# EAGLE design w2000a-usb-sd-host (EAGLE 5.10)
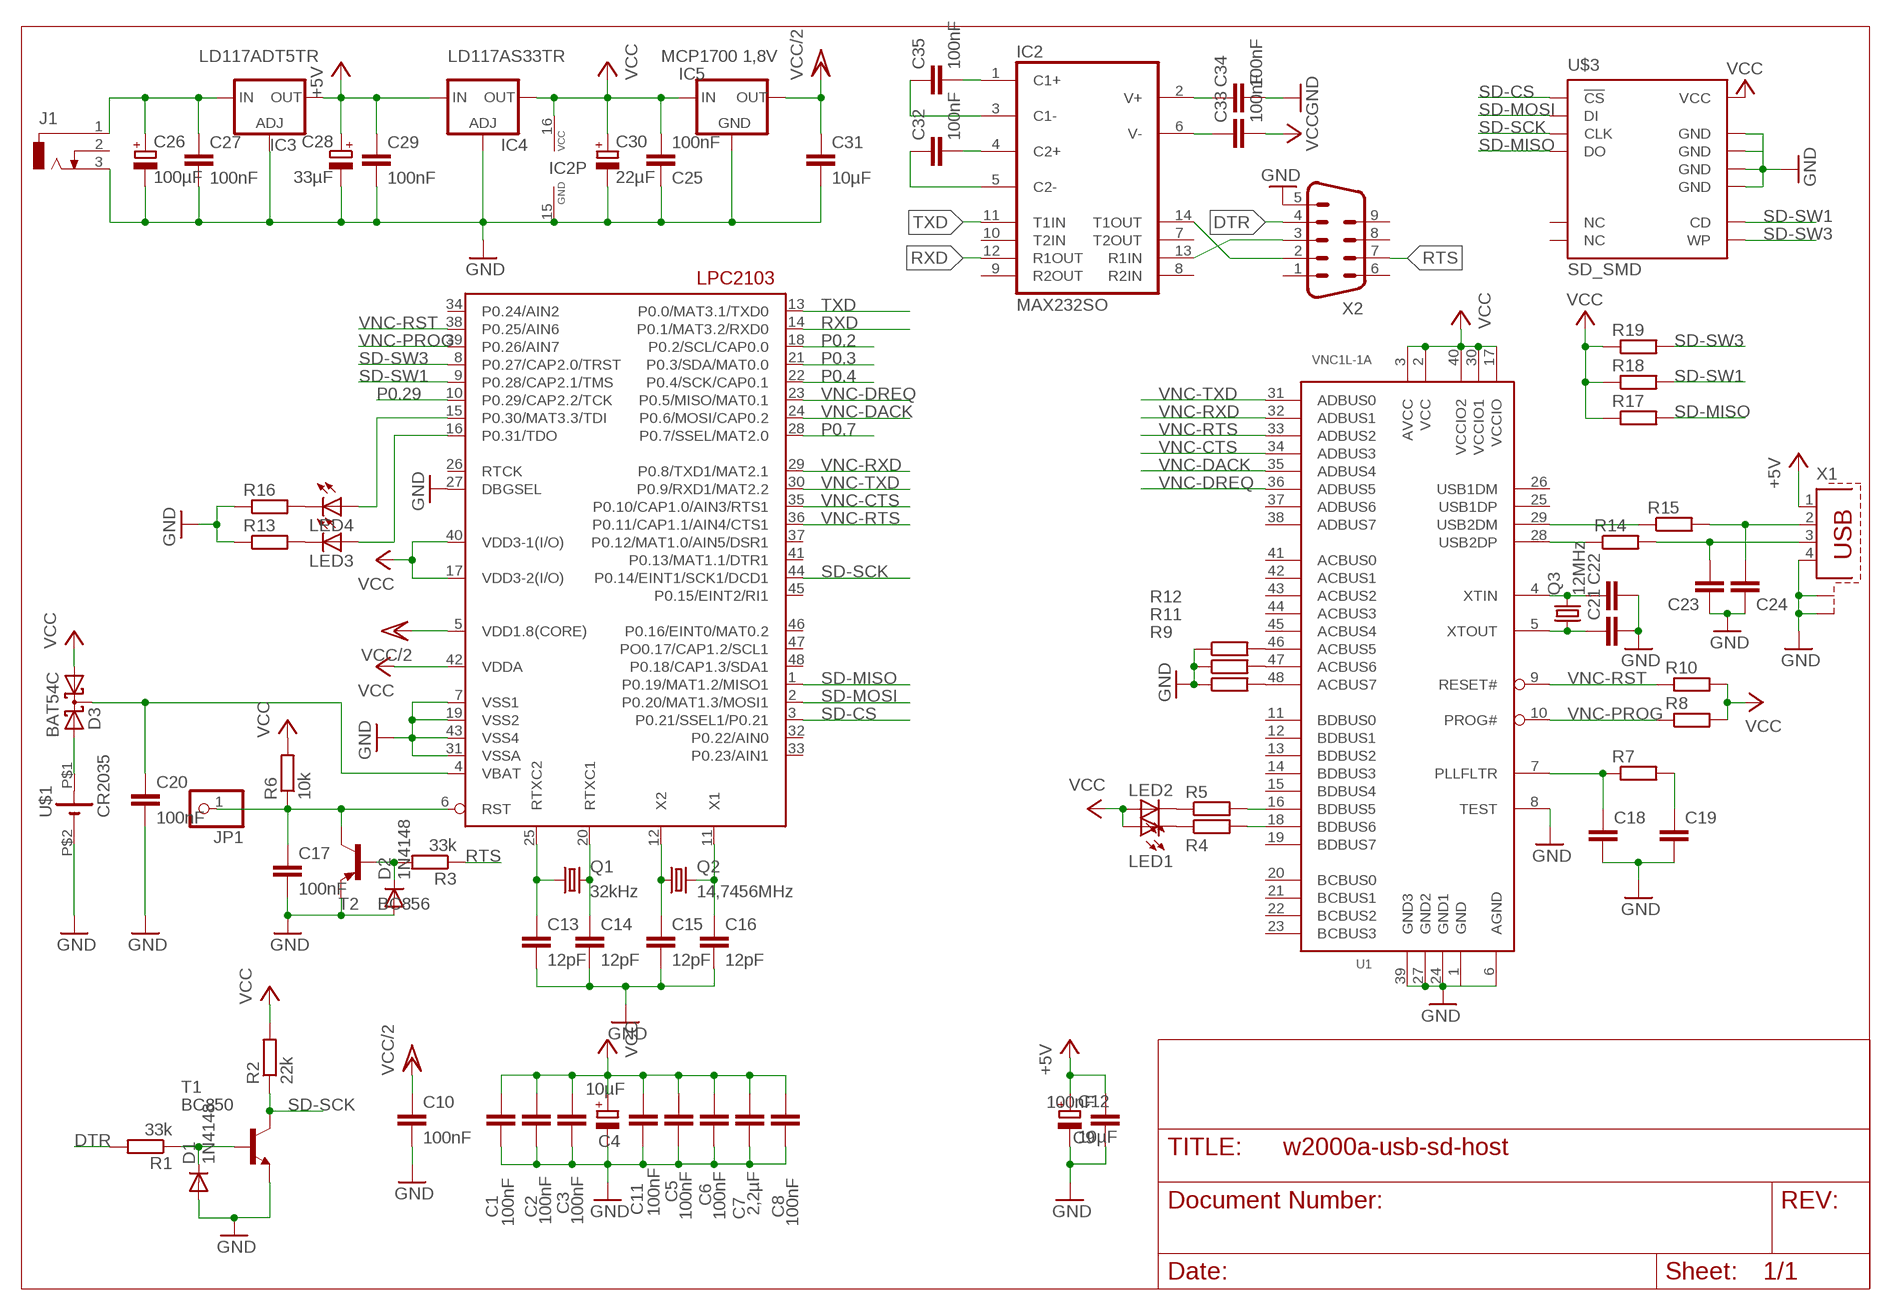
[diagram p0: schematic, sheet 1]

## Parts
C1  100nF  C-EUC0603  [C0603]
C2  100nF  C-EUC0603  [C0603]
C3  100nF  C-EUC0603  [C0603]
C4  100nF  C-EUC0603  [C0603]
C5  100nF  C-EUC0603  [C0603]
C6  100nF  C-EUC0603  [C0603]
C7  2,2µF  C-EUC0603  [C0603]
C8  100nF  C-EUC0603  [C0603]
C9  100nF  C-EUC0603  [C0603]
C10  100nF  C-EUC0603  [C0603]
C11  10µF  CPOL-EUSMCC  [SMC_C]
C12  10µF  CPOL-EUSMCC  [SMC_C]
C13  12pF  C-EUC0603  [C0603]
C14  12pF  C-EUC0603  [C0603]
C15  12pF  C-EUC0603  [C0603]
C16  12pF  C-EUC0603  [C0603]
C17  100nF  C-EUC0603  [C0603]
C18  C-EUC0603  [C0603]
C19  C-EUC0603  [C0603]
C20  100nF  C-EUC0603  [C0603]
C21  C-EUC0603  [C0603]
C22  C-EUC0603  [C0603]
C23  C-EUC0603  [C0603]
C24  C-EUC0603  [C0603]
C25  100nF  C-EUC0603  [C0603]
C26  100µF  CPOL-EUSMCD  [SMC_D]
C27  100nF  C-EUC0603  [C0603]
C28  33µF  CPOL-EUSMCB  [SMC_B]
C29  100nF  C-EUC0603  [C0603]
C30  22µF  CPOL-EU140CLH-0810  [140CLH-0810]
C31  10µF  C-EUC0603  [C0603]
C32  100nF  C-EUC0603  [C0603]
C33  100nF  C-EUC0603  [C0603]
C34  100nF  C-EUC0603  [C0603]
C35  100nF  C-EUC0603  [C0603]
D1  1N4148  1N4148MINIMELF  [MINIMELF]
D2  1N4148  1N4148MINIMELF  [MINIMELF]
D3  BAT54C  [SOT23]
IC1  LPC2103  [LQFP48]
IC2  MAX232SO  [SO16]
IC3  LD117ADT5TR  LD117ADT12TR  [DPACK]
IC4  LD117AS33TR  [SOT223]
IC5  MCP1700 1,8V  XC63FPM  [SOT23]
J1  DCJ0303  [DCJ0303]
JP1  PINHD-1X1  [1X01]
LED1  LEDCHIP-LED0603  [CHIP-LED0603]
LED2  LEDCHIP-LED0603  [CHIP-LED0603]
LED3  LED3MM  [LED3MM]
LED4  LED3MM  [LED3MM]
Q1  32kHz  QS  [QUARZ_2,0*1,2]
Q2  14,7456MHz  Q  [QUARZ_3,2*2,5]
Q3  12MHz  Q  [QUARZ_3,2*2,5]
R1  33k  R-EU_R0603  [R0603]
R2  22k  R-EU_R0603  [R0603]
R3  33k  R-EU_R0603  [R0603]
R4  R-EU_R0603  [R0603]
R5  R-EU_R0603  [R0603]
R6  10k  R-EU_R0603  [R0603]
R7  R-EU_R0603  [R0603]
R8  R-EU_R0603  [R0603]
R9  R-EU_R0603  [R0603]
R10  R-EU_R0603  [R0603]
R11  R-EU_R0603  [R0603]
R12  R-EU_R0603  [R0603]
R13  R-EU_R0603  [R0603]
R14  R-EU_R0603  [R0603]
R15  R-EU_R0603  [R0603]
R16  R-EU_R0603  [R0603]
R17  R-EU_R0603  [R0603]
R18  R-EU_R0603  [R0603]
R19  R-EU_R0603  [R0603]
T1  BC850  BC850-NPN-SOT23-BEC  [SOT23-BEC]
T2  BC856  BC856B-PNP-SOT23-BEC  [SOT23-BEC]
U1  VNC1L-1A  [LQFP48]
U$1  CR2035  [KZH-20-SMD-2]
U$3  SD_SMD  [SD]
X1  PN87520-S  [PN87520-S]
X2  M09-182  [182-009-MALE]

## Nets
+5V: C9.2 C12.+ C28.+ C29.1 IC3.4(OUT) IC4.3(IN) X1.1
DTR: R1.2 X2.4
GND: C1.1 C2.1 C3.1 C4.1 C5.1 C6.1 C7.1 C8.1 C9.1 C10.2 C11.- C12.- C13.2 C14.2 C15.2 C16.2 C17.2 C18.2 C19.2 C20.2 C21.2 C22.2 C23.1 C24.1 C25.1 C26.- C27.2 C28.- C29.2 C30.- C31.2 C34.2 D1.A D2.A IC1.7(VSS1) IC1.19(VSS2) IC1.27(DBGSEL) IC1.31(VSSA) IC1.43(VSS4) IC2.15(GND) IC3.1(ADJ) IC4.1(ADJ) IC5.1(GND) J1.3 R9.1 R11.1 R12.1 R13.1 R16.1 T1.E T2.E U1.1(GND) U1.6(AGND) U1.8(TEST) U1.24(GND1) U1.27(GND2) U1.39(GND3) U$1.P$2(-) U$3.GND U$3.GND3(GND) U$3.GND@1(GND) U$3.GND@2(GND) X1.4 X1.S1 X1.S2 X2.5
N$1: C24.2 R15.2 X1.2
N$2: C23.2 R14.2 X1.3
N$3: C13.1 IC1.25(RTXC2) Q1.P$1
N$4: C14.1 IC1.20(RTXC1) Q1.P$2
N$5: C15.1 IC1.12(X2) Q2.P$2
N$6: C16.1 IC1.11(X1) Q2.P$3
N$7: R12.2 U1.46(ACBUS5)
N$8: R14.1 U1.28(USB2DP)
N$9: R15.1 U1.29(USB2DM)
N$10: C26.+ C27.1 IC3.3(IN) J1.1
N$11: D1.C R1.1 T1.B
N$12: C22.1 Q3.P$3 U1.4(XTIN)
N$13: C21.1 Q3.P$2 U1.5(XTOUT)
N$14: LED2.C R5.1
N$15: C18.1 R7.1 U1.7(PLLFLTR)
N$16: C19.1 R7.2
N$17: D2.C R3.2 T2.B
N$18: C17.1 IC1.6(RST) JP1.1 R6.1 T2.C
N$19: IC2.14(T1OUT) X2.2
N$20: LED1.C R4.1
N$21: R11.2 U1.47(ACBUS6)
N$22: R5.2 U1.16(BDBUS5)
N$23: R4.2 U1.18(BDBUS6)
N$24: C35.2 IC2.1(C1+)
N$25: C35.1 IC2.3(C1-)
N$26: C32.2 IC2.4(C2+)
N$27: C32.1 IC2.5(C2-)
N$28: C33.1 IC2.6(V-)
N$29: C34.1 IC2.2(V+)
N$30: R9.2 U1.48(ACBUS7)
N$31: D3.2(A2) U$1.P$1(+)
N$32: IC2.13(R1IN) X2.3
N$33: LED4.K(C) R16.2
N$34: LED3.K(C) R13.2
N$35: IC1.16(P0.31/TDO) LED3.A
N$36: IC1.15(P0.30/MAT3.3/TDI) LED4.A
P0.2: IC1.18(P0.2/SCL/CAP0.0)
P0.3: IC1.21(P0.3/SDA/MAT0.0)
P0.4: IC1.22(P0.4/SCK/CAP0.1)
P0.7: IC1.28(P0.7/SSEL/MAT2.0)
P0.29: IC1.10(P0.29/CAP2.2/TCK)
RTS: R3.1 X2.7
RXD: IC1.14(P0.1/MAT3.2/RXD0) IC2.12(R1OUT)
SD-CS: IC1.3(P0.21/SSEL1/P0.21) U$3.CS(!CS)
SD-MISO: IC1.1(P0.19/MAT1.2/MISO1) R17.2 U$3.DO
SD-MOSI: IC1.2(P0.20/MAT1.3/MOSI1) U$3.DI
SD-SCK: IC1.44(P0.14/EINT1/SCK1/DCD1) R2.1 T1.C U$3.CLK
SD-SW1: IC1.9(P0.28/CAP2.1/TMS) R18.2 U$3.CD
SD-SW3: IC1.8(P0.27/CAP2.0/TRST) R19.2 U$3.WP
TXD: IC1.13(P0.0/MAT3.1/TXD0) IC2.11(T1IN)
VBAT: C20.1 D3.3(CC) IC1.4(VBAT)
VCC: C1.2 C2.2 C3.2 C4.2 C5.2 C6.2 C7.2 C8.2 C11.+ C25.2 C30.+ C33.2 D3.1(A1) IC1.17(VDD3-2(I/O)) IC1.40(VDD3-1(I/O)) IC1.42(VDDA) IC2.16(VCC) IC4.4(OUT) IC5.3(IN) LED1.A LED2.A R2.2 R6.2 R8.2 R10.2 R17.1 R18.1 R19.1 U1.2(VCC) U1.3(AVCC) U1.17(VCCIO) U1.30(VCCIO1) U1.40(VCCIO2) U$3.VCC
VCC/2: C10.1 C31.1 IC1.5(VDD1.8(CORE)) IC5.2(OUT)
VNC-CTS: IC1.35(P0.10/CAP1.0/AIN3/RTS1) U1.34(ADBUS3)
VNC-DACK: IC1.24(P0.6/MOSI/CAP0.2) U1.35(ADBUS4)
VNC-DREQ: IC1.23(P0.5/MISO/MAT0.1) U1.36(ADBUS5)
VNC-PROG: IC1.39(P0.26/AIN7) R8.1 U1.10(PROG#)
VNC-RST: IC1.38(P0.25/AIN6) R10.1 U1.9(RESET#)
VNC-RTS: IC1.36(P0.11/CAP1.1/AIN4/CTS1) U1.33(ADBUS2)
VNC-RXD: IC1.29(P0.8/TXD1/MAT2.1) U1.32(ADBUS1)
VNC-TXD: IC1.30(P0.9/RXD1/MAT2.2) U1.31(ADBUS0)
Unconnected: IC1.26(RTCK) IC1.32(P0.22/AIN0) IC1.33(P0.23/AIN1) IC1.34(P0.24/AIN2) IC1.37(P0.12/MAT1.0/AIN5/DSR1) IC1.41(P0.13/MAT1.1/DTR1) IC1.45(P0.15/EINT2/RI1) IC1.46(P0.16/EINT0/MAT0.2) IC1.47(PO0.17/CAP1.2/SCL1) IC1.48(P0.18/CAP1.3/SDA1) IC2.7(T2OUT) IC2.8(R2IN) IC2.9(R2OUT) IC2.10(T2IN) J1.2 U1.11(BDBUS0) U1.12(BDBUS1) U1.13(BDBUS2) U1.14(BDBUS3) U1.15(BDBUS4) U1.19(BDBUS7) U1.20(BCBUS0) U1.21(BCBUS1) U1.22(BCBUS2) U1.23(BCBUS3) U1.25(USB1DP) U1.26(USB1DM) U1.37(ADBUS6) U1.38(ADBUS7) U1.41(ACBUS0) U1.42(ACBUS1) U1.43(ACBUS2) U1.44(ACBUS3) U1.45(ACBUS4) U$3.NC U$3.NC@1(NC) X2.1 X2.6 X2.8 X2.9

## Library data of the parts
C1-C10 C13-C25 C27 C29 C31-C35 = rcl:C-EU: CAPACITOR, European symbol
C11 C12 C26 C28 C30 = rcl:CPOL-EU: POLARIZED CAPACITOR, European symbol
D1 D2 = diode:1N4148: DIODE
D3 = diode:BAT54C: Schottky Diodes Source: Fairchild .. BAT54.pdf
IC1 = nxp:LPC2103: LPC2101/2102/2103 microcontroler from Philips
IC2 = maxim:MAX232: RS232 TRANSEIVER
IC3 IC4 = v-reg:LD117A?*: Low drop fixed and adjustable positive voltage regulators 1 A Source: http://www.st.com/stonline/products/literature/ds/7194/ld1117axx.pdf
IC5 = v-reg:XC63FP: Positiv Voltage Regulators www.torex.co.jp/english/product/pro02/pdf/0201_xc62fp.pdf
J1 = con-jack:DCJ0303: DC POWER JACK Source: DCJ0303.pdf
JP1 = pinhead:PINHD-1X1: PIN HEADER
LED1-LED4 = led:LED: LED
Q1-Q3 = _kurt:Q
R1-R19 = rcl:R-EU_: RESISTOR, European symbol
T1 = transistor:*-NPN-: NPN Transistror BF959 corrected 2008.03.06
T2 = transistor:*-PNP-: PNP Transistror
U1 = ftdichip-1:VNC1L
U$1 = _kurt:CR2035
U$3 = SD-Card:SD: CSD-Electronics: 020-SDH2
X1 = con-berg:PN87520-S
X2 = con-subd:M09: SUB-D

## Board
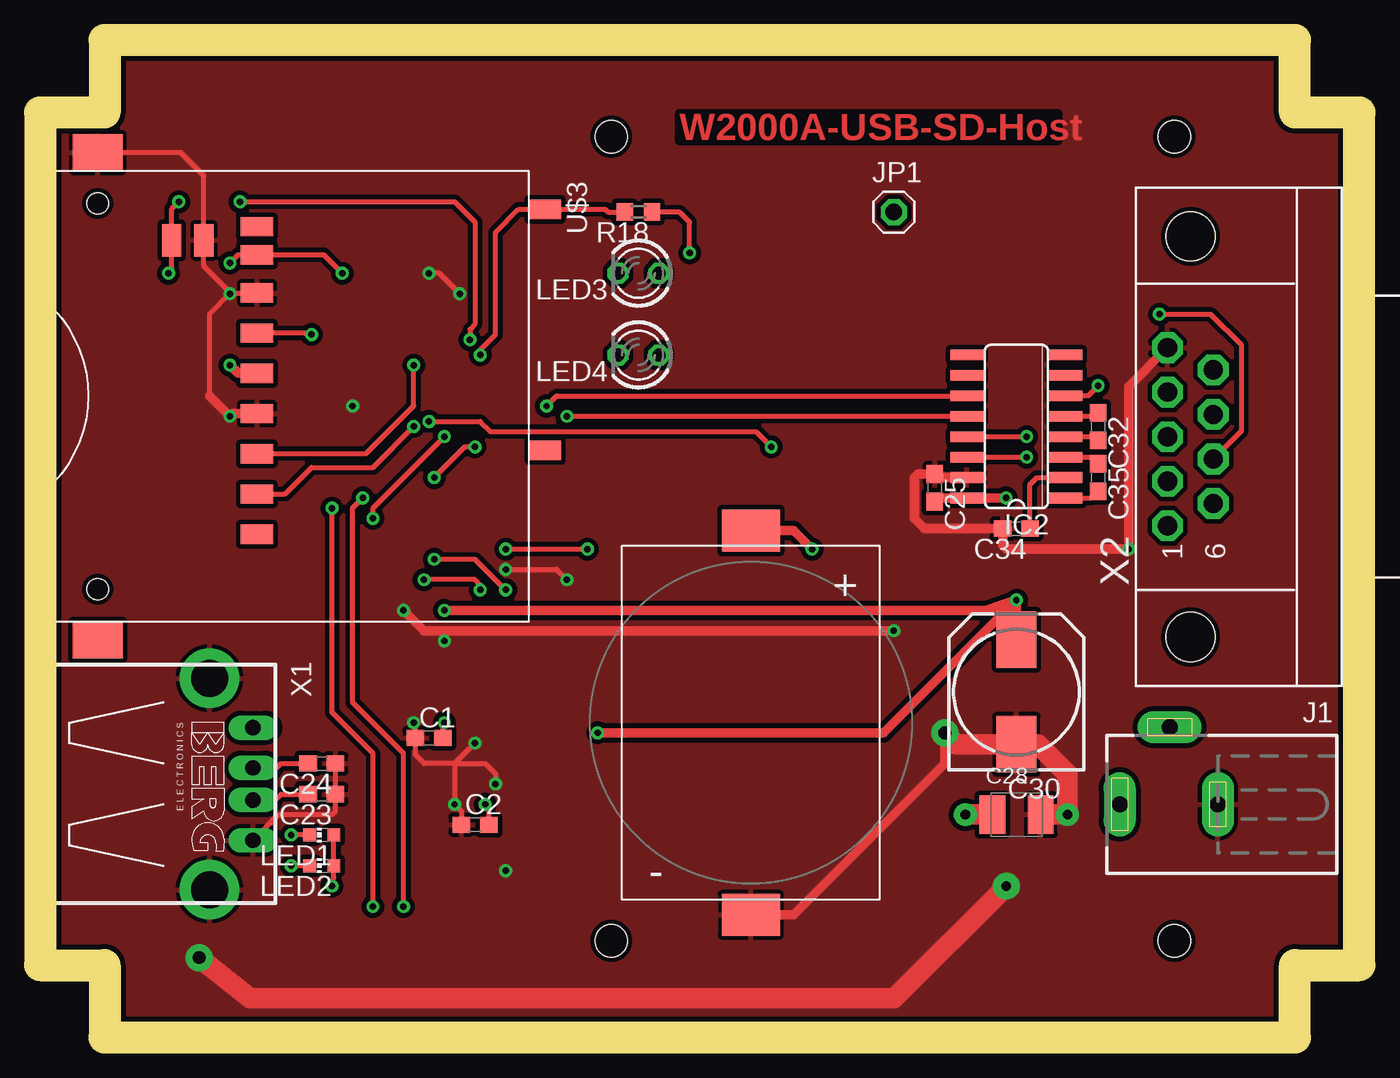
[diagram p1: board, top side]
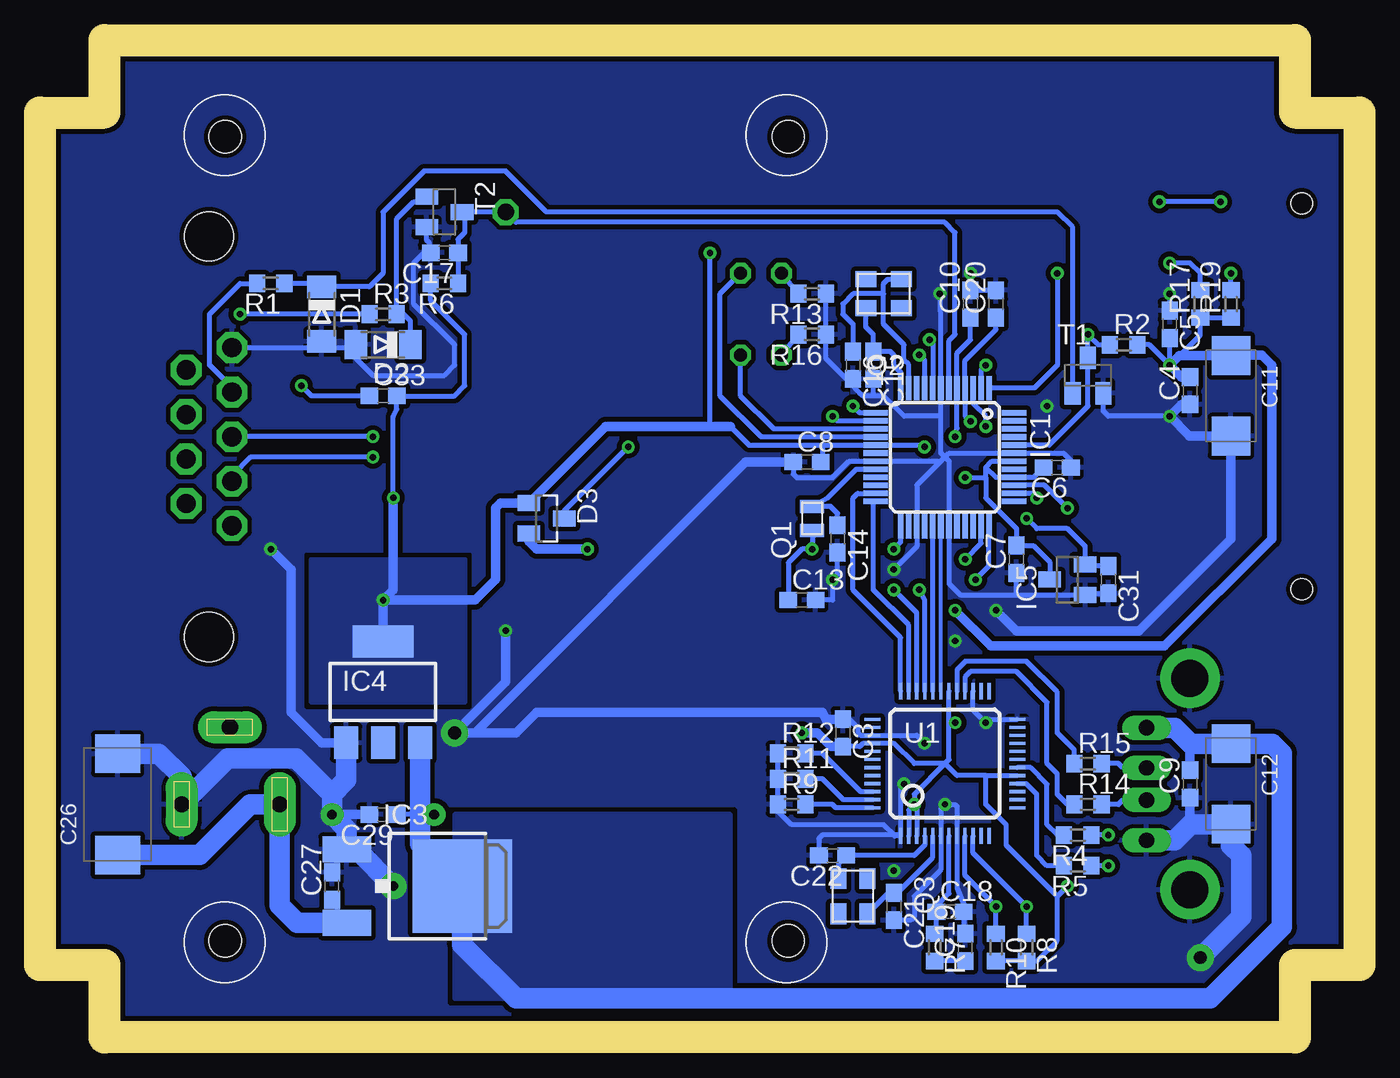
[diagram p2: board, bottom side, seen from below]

Size 82 x 62 mm. Coordinates in mm from the lower left corner, seen from the top.
Copper layers (1*16): Top 0.035mm / dielectric 1.5mm / Bottom 0.035mm
Design rules "HAKA_35_L2 *": minimum track width 0.15mm, minimum drill 0.3mm, track to track 0.15mm, track to pad 0.15mm, pad to pad 0.15mm, via to via 0.15mm, smd to smd 0mil, copper to edge 0.2mm, drill to drill 0.2mm, minimum pad ring 0.15mm, minimum via ring 0.15mm, stop-mask expansion 0.1mm, vias tented up to drill 0mil, thermal gap 10mil

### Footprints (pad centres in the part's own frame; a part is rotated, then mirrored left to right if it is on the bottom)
C0603 = smd 1.1 x 1: 1 -0.85,0; 2 0.85,0
SMC_C = smd 2.4 x 2.4: + -2.5,0; - 2.5,0
SMC_D = smd 2.4 x 2.8: + -3.15,0; - 3.15,0
SMC_B = smd 1.6 x 2.4: + -1.5,0; - 1.5,0
140CLH-0810 = smd 3.5 x 2.5: + 3.25,0; - -3.25,0
MINIMELF = smd 1.4 x 1.8: A 1.7,0; C -1.7,0
SOT23 = smd 1 x 1.4: 1 -0.95,-1.1; 2 0.95,-1.1; 3 0,1.1
LQFP48 = smd 1.5 x 0.35: 1 -4.3,2.75; 2 -4.3,2.25; 3 -4.3,1.75; 4 -4.3,1.25; 5 -4.3,0.75; 6 -4.3,0.25; 7 -4.3,-0.25; 8 -4.3,-0.75; 9 -4.3,-1.25; 10 -4.3,-1.75; 11 -4.3,-2.25; 12 -4.3,-2.75; 25 4.3,-2.75; 26 4.3,-2.25; 27 4.3,-1.75; 28 4.3,-1.25; 29 4.3,-0.75; 30 4.3,-0.25; 31 4.3,0.25; 32 4.3,0.75; 33 4.3,1.25; 34 4.3,1.75; 35 4.3,2.25; 36 4.3,2.75 | smd 0.35 x 1.5: 13 -2.75,-4.3; 14 -2.25,-4.3; 15 -1.75,-4.3; 16 -1.25,-4.3; 17 -0.75,-4.3; 18 -0.25,-4.3; 19 0.25,-4.3; 20 0.75,-4.3; 21 1.25,-4.3; 22 1.75,-4.3; 23 2.25,-4.3; 24 2.75,-4.3; 37 2.75,4.3; 38 2.25,4.3; 39 1.75,4.3; 40 1.25,4.3; 41 0.75,4.3; 42 0.25,4.3; 43 -0.25,4.3; 44 -0.75,4.3; 45 -1.25,4.3; 46 -1.75,4.3; 47 -2.25,4.3; 48 -2.75,4.3
SO16 = smd 0.66 x 2.032: 1 -4.445,-3.073; 2 -3.175,-3.073; 3 -1.905,-3.073; 4 -0.635,-3.073; 5 0.635,-3.073; 6 1.905,-3.073; 7 3.175,-3.073; 8 4.445,-3.073; 9 4.445,3.073; 10 3.175,3.073; 11 1.905,3.073; 12 0.635,3.073; 13 -0.635,3.073; 14 -1.905,3.073; 15 -3.175,3.073; 16 -4.445,3.073
DPACK = smd 1.6 x 3: 1 -2.28,-4.8; 3 2.28,-4.8 | smd 5.8 x 6.2: 4 0,2.38
SOT223 = smd 1.5 x 2: 1 -2.3,-3.15; 2 0,-3.15; 3 2.3,-3.15 | smd 3.8 x 2: 4 0,3.15
DCJ0303 = drill 1 pad 2 long: 1 0,3.1; 2 4.8,0; 3 0,-3
1X01 = drill 1.016 octagon: 1 0,0
CHIP-LED0603 = smd 0.8 x 0.8: A 0,-0.75; C 0,0.75
LED3MM = drill 0.813 octagon: A -1.27,0; K 1.27,0
QUARZ_2,0*1,2 = smd 0.8 x 1.5: P$1 -0.75,0; P$2 0.75,0
QUARZ_3,2*2,5 = smd 1.3 x 1: P$1 -1.1,0.9; P$2 1.1,0.9; P$3 -1.1,-0.9; P$4 1.1,-0.9
R0603 = smd 1 x 1.1: 1 -0.85,0; 2 0.85,0
SOT23-BEC = smd 1 x 1.4: B -0.95,-1.1; C 0,1.1; E 0.95,-1.1
LQFP48' = smd 0.2 x 1: 1 -2.75,-4.5; 2 -2.25,-4.5; 3 -1.75,-4.5; 4 -1.25,-4.5; 5 -0.75,-4.5; 6 -0.25,-4.5; 7 0.25,-4.5; 8 0.75,-4.5; 9 1.25,-4.5; 10 1.75,-4.5; 11 2.25,-4.5; 12 2.75,-4.5; 25 2.75,4.5; 26 2.25,4.5; 27 1.75,4.5; 28 1.25,4.5; 29 0.75,4.5; 30 0.25,4.5; 31 -0.25,4.5; 32 -0.75,4.5; 33 -1.25,4.5; 34 -1.75,4.5; 35 -2.25,4.5; 36 -2.75,4.5 | smd 1 x 0.2: 13 4.5,-2.75; 14 4.5,-2.25; 15 4.5,-1.75; 16 4.5,-1.25; 17 4.5,-0.75; 18 4.5,-0.25; 19 4.5,0.25; 20 4.5,0.75; 21 4.5,1.25; 22 4.5,1.75; 23 4.5,2.25; 24 4.5,2.75; 37 -4.5,2.75; 38 -4.5,2.25; 39 -4.5,1.75; 40 -4.5,1.25; 41 -4.5,0.75; 42 -4.5,0.25; 43 -4.5,-0.25; 44 -4.5,-0.75; 45 -4.5,-1.25; 46 -4.5,-1.75; 47 -4.5,-2.25; 48 -4.5,-2.75
KZH-20-SMD-2 = smd 3.6 x 2.6: P$1 0,11.95; P$2 0,-11.95
STRAPUBOX-2062_ = hole 2: -29.5,25; 5.5,25; -29.5,-25; 5.5,-25
SD = smd 1.2 x 2: CD 2.37,31.65; CLK 10.07,13.75; CS 20.07,13.75; DI 17.57,13.75; DO 5.2,13.75; GND 15.07,13.75; GND@1 7.57,13.75; GND@5 17.35,31.65; NC 3.45,13.75; NC@1 22.57,13.75; VCC 12.57,13.75 | smd 2.3 x 3.1: GND3 -1.15,3.85; GND@4 29.15,3.85 | smd 2 x 1.2: GND@2 4.3,10.45; WP 4.3,8.45 | hole 1.3: 2,3.85; 26,3.85
PN87520-S = drill 0.95 long: 1 -3.5,2.71; 2 -1,2.71; 3 1,2.71; 4 3.5,2.71 | drill 2.3 pad 2.9 round: S1 -6.57,0; S2 6.57,0
182-009-MALE = drill 1.194 pad 1.524 octagon: 1 -5.537,10.923; 2 -2.769,10.923; 3 0,10.923; 4 2.769,10.923; 5 5.537,10.923; 6 -4.153,8.08; 7 -1.384,8.08; 8 1.384,8.08; 9 4.153,8.08 | hole 3.048: -12.446,9.501; 12.446,9.501

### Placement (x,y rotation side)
C1  24.17,18.62 0 top
C2  27.03,13.22 0 top
C3  32.11,18.94 270 bottom
C4  10.52,40.21 90 bottom
C5  11.79,44.34 270 bottom
C6  18.78,35.45 180 bottom
C7  21.32,29.73 90 bottom
C8  34.33,35.76 0 bottom
C9  10.52,15.76 90 bottom
C10  24.17,45.61 90 bottom
C11  7.98,39.89 270 bottom
C12  7.98,15.76 270 bottom
C13  34.65,27.19 0 bottom
C14  32.43,31 270 bottom
C15  30.21,41.8 270 bottom
C16  31.48,41.8 270 bottom
C17  56.88,48.78 180 bottom
C18  25.44,7.82 0 bottom
C19  24.49,5.6 90 bottom
C20  22.59,45.61 90 bottom
C21  28.94,8.14 270 bottom
C22  32.75,11.32 180 bottom
C23  17.51,15.13 180 top
C24  17.51,17.03 180 top
C25  55.61,34.17 270 top
C26  77.19,14.49 90 bottom
C27  63.86,9.41 90 bottom
C28  60.69,13.86 0 top
C29  60.69,13.86 180 bottom
C30  60.69,21.48 90 top
C31  15.6,28.46 270 bottom
C32  65.77,37.98 270 top
C33  60.69,39.89 0 bottom
C34  60.69,31.64 180 top
C35  65.77,34.81 270 top
D1  64.5,44.97 270 bottom
D2  60.69,43.06 180 bottom
D3  50.52,32.27 270 bottom
IC1  25.76,36.08 270 bottom
IC2  60.69,37.98 90 top
IC3  58.15,9.41 270 bottom
IC4  60.69,21.48 0 bottom
IC5  18.14,28.46 90 bottom
J1  70.21,14.49 90 top
JP1  53.07,51.32 0 top
LED1  17.51,12.59 90 top
LED2  17.51,10.68 90 top
LED3  37.19,47.51 180 top
LED4  37.19,42.43 180 top
Q1  34.02,32.27 90 bottom
Q2  29.57,46.24 180 bottom
Q3  31.48,8.78 270 bottom
R1  67.67,46.88 180 bottom
R2  14.65,43.06 0 bottom
R3  60.69,44.97 0 bottom
R4  17.51,12.59 180 bottom
R5  17.51,10.68 180 bottom
R6  56.88,46.88 180 bottom
R7  26.4,5.6 270 bottom
R8  20.68,5.6 270 bottom
R9  35.29,14.49 0 bottom
R10  22.59,5.6 270 bottom
R11  35.29,16.08 0 bottom
R12  35.29,17.67 0 bottom
R13  34.02,46.24 180 bottom
R14  16.87,14.49 0 bottom
R15  16.87,17.03 0 bottom
R16  34.02,43.7 180 bottom
R17  9.89,45.61 90 bottom
R18  37.19,51.32 180 top
R19  7.98,45.61 90 bottom
T1  16.87,41.16 0 bottom
T2  56.88,51.32 270 bottom
U1  VNC1L-1A  [LQFP48']  25.76,17.03 0 bottom
U$1  44.18,19.57 0 top
U$2  [STRAPUBOX-2062_]  41,31 180 top
U$3  -0.27,53.86 270 top
X1  10.52,15.76 270 top
X2  81,37.35 90 top

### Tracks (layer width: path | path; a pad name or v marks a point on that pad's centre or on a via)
+5V  (via drill 0.6 pad 1.42)
  Top 1.27: v57.51,13.86 C28.+
  Bottom 0.3: IC3.4 58.38,12.03 | 58.38,13.86 C29.1
  Bottom 0.6: C9.2 10.52,18.22 10.48,18.26
  Bottom 1.27: 58.38,12.03 58.38,13.86 | 58.38,13.86 IC4.3 | IC3.4 55.77,5.76 52.43,2.43 9.25,2.43 4.81,6.87 4.81,17.67 5.4,18.26 C12.+ 10.48,18.26 11.48,19.26 X1.1 | 58.38,13.86 v57.51,13.86
  pour Bottom (no thermals): 56.24,13.86 56.24,2.43 39.09,2.43 39.09,13.86
DTR
  Bottom 0.3: X2.4 70.08,40.4 71.48,41.8 71.48,44.97 69.57,46.88 R1.2
GND  (via drill 0.4 pad 0.8, 0.6 pad 1.42, 0.6 pad 1.68, 0.8 pad 1.68)
  Top 0.3: C24.1 C23.1 18.36,14.07 18.14,13.86 14.83,13.86 X1.4 | v28.94,29.1 32.11,29.1 v32.75,28.46 | 55.82,34.81 C25.1 55.61,35.45 | v11.79,38.62 11.96,38.79 | 11.84,46.29 U$3.GND@1 | 11.84,46.29 v11.79,46.24 10.52,44.97 10.52,39.89 | 11.84,46.29 10.18,47.95 U$3.GND@2 10.18,53.57 8.74,55.01 U$3.GND3 | C2.1 26.18,14.07 v25.76,14.49 25.76,17.03 | v23.22,19.57 23.32,19.47 C1.1 23.32,17.56 23.86,17.03 25.76,17.03 | v27.03,18.3 25.76,17.03 | 25.76,17.03 27.67,17.03 28.3,16.4 v28.3,15.76 | v24.17,47.51 24.81,47.51 v26.08,46.24
  Top 0.6: 55.82,34.81 IC2.15 | C25.1 54.55,35.03 54.34,34.81 54.34,32.27 54.97,31.64 C34.2 59.84,30.58 60.05,30.37 v67.67,30.37 67.67,40.48 X2.5 | 11.96,38.79 U$3.GND | v11.79,38.62 10.52,39.89 | v53.07,25.29 23.86,25.29 v22.59,26.56 | U$1.P$2 46.83,7.62 56.24,17.03 v56.24,18.94
  Top 1.27: C28.- v63.86,13.86 63.86,16.4 62.03,18.23 C30.- | v9.89,4.97 13.06,2.43 53.07,2.43 v60.05,9.41 | C30.- 60.61,18.3 | C30.- 56.95,18.23 v56.24,18.94
  Bottom 0.3: 25.76,36.08 25.51,35.83 IC1.31 25.51,28.21 24.81,27.51 21.32,27.51 | 26.01,35.83 27.51,34.33 IC1.27 27.51,30.52 v28.94,29.1 | 26.01,35.83 IC1.19 31.73,35.83 32.75,34.81 34.97,34.81 35.18,35.03 C8.1 | 26.01,35.83 25.76,36.08 | 25.76,36.08 25.51,36.33 IC1.43 18.39,36.33 17.93,35.86 C6.1 | 26.01,38.62 26.01,36.33 25.76,36.08 | 26.01,38.62 IC1.7 26.01,44.72 v26.08,46.24 | R12.1 R11.1 R9.1 36.13,14.07 35.29,13.22 29.57,13.22 28.88,12.53 U1.1 | U1.1 28.51,15.55 v28.3,15.76 | C13.2 32.75,27.19 v32.75,28.46 32.43,28.78 C14.2 | C21.2 27.88,7.29 27.67,7.51 27.67,8.78 26.01,10.43 U1.6 26.01,14.24 v25.76,14.49 25.12,14.49 25.01,14.38 U1.8 25.01,9.3 24.59,8.24 C18.2 24.59,6.55 C19.2 | 26.01,38.62 28.3,38.62 29.57,39.89 30.21,39.89 | C27.2 63.23,11.41 IC3.1 | X2.5 64.5,42.89 | 64.5,42.89 62.56,42.89 D2.A 62.38,42.23 61.32,41.16 56.88,41.16 56.24,41.8 56.24,43.06 58.78,45.61 58.78,48.14 58.15,48.78 C17.2 57.8,48.78 57.8,49.39 57.98,49.56 T2.E | 64.5,42.89 D1.A | R13.1 R16.1 33.16,42.22 31.79,40.84 | T1.E 15.92,38.94 15.6,38.62 v11.79,38.62 | 21.32,27.51 IC5.1 16.94,27.61 C31.2 | v27.03,18.3 27.51,18.78 U1.39 31,18.78 31.16,18.94 31.16,19.25 31.69,19.79 C3.1 | U1.24 23.01,19.78 v23.22,19.57 24.01,20.36 U1.27 | v11.79,46.24 C5.1 | C22.2 33.59,12.37 33.38,12.59 28.57,12.59 U1.1 | 21.32,27.51 C7.1 | 30.21,39.89 30.84,39.89 31.79,40.84 | 30.21,39.89 C15.2 | C16.2 31.69,40.95 31.79,40.84 | C20.2 C10.2 v24.17,47.51
  Bottom 0.6: v67.67,30.37 66.4,29.1 66.4,20.21 64.52,18.33 IC4.1 | v22.59,26.56 21.32,25.29 13.7,25.29 7.98,31 C11.- 10.56,37.39 v11.79,38.62 11.05,39.36 C4.1 | C9.1 10.52,13.3 10.48,13.26 | C3.1 33.16,19.79 33.38,20.21 51.16,20.21 52.43,18.94 54.97,18.94 | C8.1 38.14,35.76 54.97,18.94 | v63.86,13.86 C29.2 | 54.97,18.94 v56.24,18.94 53.07,22.11 v53.07,25.29
  Bottom 1.27: v9.89,4.97 7.35,7.51 7.35,11.32 7.98,11.95 C12.- 10.48,13.26 11.48,12.26 X1.4 | C26.- 74.63,17.64 73.21,16.22 J1.3 70.35,17.35 66.08,17.35 63.86,15.13 | 63.86,15.13 v63.86,13.86 62.95,12.94 IC3.1 62.33,11.69 v60.05,9.41 | IC4.1 62.98,16 63.86,15.13
  other vias: 19.41,39.25 25.12,24.65 28.94,10.36
  pour Top (isolate 0.3): -0.27,57.67 4.17,57.67 4.17,62.11 77.83,62.11 77.83,57.67 82.28,57.67 82.28,4.97 77.83,4.97 77.83,-0.11 4.17,-0.11 4.17,4.33 -0.27,4.33
  pour Bottom (isolate 0.3, rank 2): -0.27,57.67 4.17,57.67 4.17,62.11 77.83,62.11 77.83,57.67 82.28,57.67 82.28,4.97 77.83,4.97 77.83,-0.11 4.17,-0.11 4.17,4.33 -0.27,4.33
N$1
  Top 0.3: X1.2 14.7,16.76 14.97,17.03 C24.2
  Bottom 0.3: X1.2 14.7,16.76 14.97,17.03 R15.2
N$2
  Top 0.3: X1.3 14.6,14.76 14.97,15.13 C23.2
  Bottom 0.3: X1.3 14.7,14.76 14.97,14.49 R14.2
N$3  (via drill 0.4 pad 0.8)
  Top 0.3: v28.94,30.37 v34.02,30.37
  Bottom 0.3: IC1.25 28.51,30.79 v28.94,30.37 | Q1.P$1 33.9,31.52 v34.02,30.37 34.65,30.37 35.5,29.52 C13.1
N$4
  Bottom 0.3: IC1.20 31.27,35.33 33.06,33.54 Q1.P$2 32.86,33.02 32.43,32.59 C14.1
N$5
  Bottom 0.3: Q2.P$2 30.67,44.17 30.21,43.7 C15.1 29.15,42.64 28.94,42.43 28.94,41.8 28.51,41.37 IC1.12
N$6
  Bottom 0.3: IC1.11 28.01,41.82 28.3,42.11 28.3,43.06 29.57,44.34 29.57,46.24 | Q2.P$3 29.3,47.14 29.57,46.88 29.57,46.24 | C16.1 31.48,44.34 32.11,44.97 32.11,45.61 31.48,46.24 29.57,46.24
N$7
  Bottom 0.3: U1.46 31,15.28 33.38,17.67 R12.2
N$8
  Bottom 0.3: U1.28 24.51,22.41 24.17,22.75 21.32,22.75 19.41,20.84 19.41,17.03 18.78,16.4 18.78,15.13 18.14,14.49 R14.1
N$9
  Bottom 0.3: U1.29 25.01,22.86 24.49,23.38 20.68,23.38 18.78,21.48 18.78,18.94 17.72,17.88 R15.1
N$10
  Bottom 0.3: C27.1 63.23,7.41 IC3.3
  Bottom 1.27: IC3.3 66.03,7.13 67.11,8.22 J1.1 68.94,14.49 72.09,11.34 C26.+
N$11
  Bottom 0.3: R1.1 64.7,46.88 D1.C 61.52,46.67 60.69,47.51 60.69,51.32 58.15,53.86 53.07,53.86 50.52,51.32 18.78,51.32 17.82,50.36 T1.B
N$12
  Bottom 0.3: U1.4 27.01,11.97 27.67,11.32 C22.1 32.38,10.84 Q3.P$3
N$13
  Bottom 0.3: U1.5 26.51,11.2 28.72,8.99 C21.1 29.26,8.99 Q3.P$2 30.58,7.77
N$14  (via drill 0.4 pad 0.8)
  Top 0.3: LED2.C v15.6,10.68
  Bottom 0.3: v15.6,10.68 R5.1
N$15
  Bottom 0.3: U1.7 25.51,8.95 26.29,8.16 C18.1 26.29,6.55 R7.1
N$16
  Bottom 0.3: C19.1 R7.2
N$17
  Bottom 0.3: T2.B 58.29,51.95 58.78,51.95 59.84,50.9 R3.2 59.41,44.97 58.98,44.54 D2.C
N$18
  Bottom 0.3: IC1.6 25.51,43.31 25.12,43.7 25.12,50.05 25.76,50.69 52.43,50.69 JP1.1 T2.C 55.61,51.15 55.61,50.05 56.02,49.63 C17.1 R6.1
N$19  (via drill 0.4 pad 0.8)
  Top 0.3: IC2.14 v61.32,36.08
  Bottom 0.3: X2.2 70.08,34.94 68.94,36.08 v61.32,36.08
N$20  (via drill 0.4 pad 0.8)
  Top 0.3: LED1.C v15.6,12.59
  Bottom 0.3: v15.6,12.59 R4.1
N$21
  Bottom 0.3: U1.47 32.08,14.78 33.38,16.08 R11.2
N$22
  Bottom 0.3: R5.2 19.41,10.68 20.05,11.32 20.05,15.13 20.7,15.78 U1.16
N$23
  Bottom 0.3: R4.2 18.78,12.59 19.41,13.22 19.41,15.76 20.43,16.78 U1.18
N$24
  Top 0.3: IC2.1 65.34,33.54 C35.2
N$25
  Top 0.3: IC2.3 65.34,36.08 C35.1
N$26
  Top 0.3: IC2.4 65.55,37.35 C32.2
N$27
  Top 0.3: IC2.5 65.55,38.62 C32.1
N$28  (via drill 0.4 pad 0.8)
  Top 0.3: v65.77,40.53 65.13,39.89 IC2.6
  Bottom 0.3: C33.1 65.13,39.89 v65.77,40.53
N$29
  Top 0.3: C34.1 61.54,34.39 61.95,34.81 IC2.2
N$30
  Bottom 0.3: 34.23,14.28 R9.2 32.75,14.49 32.54,14.28 U1.48
N$31  (via drill 0.4 pad 0.8)
  Top 0.6: U$1.P$1 46.83,31.52 v47.98,30.37
  Bottom 0.6: D3.2 51.62,30.83 51.16,30.37 v47.98,30.37
N$32  (via drill 0.4 pad 0.8)
  Top 0.3: IC2.13 v61.32,37.35
  Bottom 0.3: v61.32,37.35 X2.3
N$33
  Bottom 0.3: LED4.K R16.2
N$34
  Bottom 0.3: R13.2 LED3.K
N$35
  Bottom 0.3: IC1.16 37.17,37.33 39.73,39.89 39.73,46.24 LED3.A
N$36
  Bottom 0.3: IC1.15 36.4,37.83 38.46,39.89 LED4.A
RTS  (via drill 0.4 pad 0.8)
  Top 0.3: v69.57,44.97 72.75,44.97 74.66,43.06 74.66,37.7 X2.7
  Bottom 0.3: R3.1 v69.57,44.97
RXD  (via drill 0.4 pad 0.8)
  Top 0.3: v32.75,38.62 IC2.12
  Bottom 0.3: IC1.14 32.45,38.33 v32.75,38.62
SD-CS  (via drill 0.4 pad 0.8)
  Top 0.3: v23.22,37.98 20.68,35.45 16.87,35.45 15.22,33.79 U$3.CS
  Bottom 0.3: IC1.3 24.01,39.41 23.22,38.62 v23.22,37.98
SD-MISO  (via drill 0.4 pad 0.8)
  Top 0.3: v11.79,48.14 12.31,48.66 U$3.DO 17.62,48.66 v18.78,47.51
  Bottom 0.3: IC1.1 20.19,40.38 18.78,41.8 v18.78,47.51 | v11.79,48.14 10.52,48.14 9.89,47.51 R17.2
SD-MOSI  (via drill 0.4 pad 0.8)
  Top 0.3: U$3.DI 20.26,36.29 23.22,39.25 v23.22,41.8
  Bottom 0.3: IC1.2 23.51,41.5 v23.22,41.8
SD-SCK  (via drill 0.4 pad 0.8)
  Top 0.3: U$3.CLK 16.46,43.79 v16.87,43.7
  Bottom 0.3: IC1.44 19.3,36.83 16.87,39.25 T1.C v16.87,43.7 16.24,43.06 R2.1
SD-SW1  (via drill 0.4 pad 0.8)
  Top 0.3: v27.35,42.43 27.35,42.75 28.3,43.7 28.3,50.05 29.74,51.49 U$3.CD 35.12,51.49 35.29,51.32 R18.2
  Bottom 0.3: IC1.9 27.01,42.09 v27.35,42.43
SD-SW3  (via drill 0.4 pad 0.8)
  Top 0.3: v26.71,43.38 26.71,44.02 27.03,44.34 27.03,50.69 25.76,51.95 v12.43,51.95 | v7.98,47.51 8.18,47.7 U$3.WP 8.18,51.52 v8.62,51.95
  Bottom 0.3: IC1.8 26.51,43.18 v26.71,43.38 | R19.2 v7.98,47.51 | v8.62,51.95 v12.43,51.95
TXD  (via drill 0.4 pad 0.8)
  Top 0.3: IC2.11 32.11,39.89 v31.48,39.25
  Bottom 0.3: IC1.13 31.05,38.83 v31.48,39.25
VBAT  (via drill 0.4 pad 0.8)
  Top 0.3: v24.17,38.3 27.35,38.3 27.98,37.67 44.49,37.67 v45.45,36.72
  Bottom 0.3: v24.17,38.3 24.51,38.64 IC1.4 24.51,42.09 22.59,44.02 C20.1 | D3.3 49.43,32.73 v45.45,36.72
VCC  (via drill 0.4 pad 0.8)
  Top 0.3: v27.03,36.72 26.4,36.72 v24.49,34.81 | IC2.16 57.51,33.44 | 55.82,33.54 C25.2 | LED1.A LED2.A 18.26,9.93 v18.14,9.41 | C2.2 27.88,14.28 v27.67,14.49 | C1.2 25.02,19.47 v25.12,19.57 | R18.1 39.73,51.32 40.37,50.69 v40.37,48.78
  Top 0.6: v60.05,33.54 IC2.16 55.82,33.54 | v60.69,27.19 C30.+ | v60.69,27.19 52.43,18.94 v34.65,18.94 | U$3.VCC 12.3,41.29 v11.79,41.8 | v60.69,27.19 58.78,26.56 v25.12,26.56
  Bottom 0.3: IC1.42 22.84,35.83 23.22,35.45 | 23.22,35.45 22.61,34.83 IC1.40 20.24,34.83 C6.2 | 25.51,19.57 25.51,17.28 25.76,17.03 | 25.51,19.57 U1.30 | 23.22,16.28 U1.17 | 23.22,16.28 25.01,16.28 25.76,17.03 | 23.22,34.81 23.22,33.54 21.32,31.64 C7.2 20.26,30.58 19.24,29.56 IC5.3 | 23.22,34.81 23.22,35.45 | 18.78,8.78 21.95,11.95 21.95,13.22 23.22,14.49 23.22,16.28 | 18.78,8.78 18.78,6.02 20.05,4.75 R8.2 R10.2 | v27.03,36.72 27.15,36.83 IC1.17 33.38,36.83 | v24.49,34.81 23.22,34.81 | 33.38,36.83 37.94,36.83 39.09,37.98 | R6.2 57.73,45.82 55.61,43.7 55.61,40.53 56.24,39.89 C33.2 59.84,39.04 60.05,38.62 v60.05,33.54 | 11.2,42.39 11.16,42.39 9.89,43.66 R17.1 R19.1 | 40.37,37.98 v40.37,48.78 | 18.78,8.78 v18.14,9.41 | 25.76,17.03 27.67,17.03 28.92,18.28 U1.40 30.86,18.28 31.05,18.09 C3.2 | U1.2 28.01,14.15 v27.67,14.49 | U1.3 27.51,14.34 v27.67,14.49 | 25.76,17.03 27.67,15.13 v27.67,14.49 | 25.51,19.57 v25.12,19.57 | C5.2 v11.79,41.8 13.06,43.06 R2.2 | C8.2 33.38,35.76 33.38,36.83
  Bottom 0.6: 39.09,37.98 40.37,37.98 46.86,37.98 D3.1 53.38,33.22 53.7,32.91 53.7,28.46 54.97,27.19 v60.69,27.19 | v60.69,27.19 IC4.4 | v60.69,27.19 60.05,27.83 v60.05,33.54 | 11.16,42.39 C11.+ 7.98,42.43 6.08,42.43 5.44,41.8 5.44,31 12.11,24.33 22.9,24.33 v25.12,26.56 | 11.2,42.39 v11.79,41.8 11.05,41.06 C4.2 | v34.65,18.94 33.7,18.94 32.85,18.09 C3.2
  pour Bottom (no thermals): 55.61,20.84 65.13,20.84 65.13,29.73 55.61,29.73
VCC/2  (via drill 0.4 pad 0.8)
  Top 0.3: v20.68,32.27 20.68,32.91 v25.12,37.35
  Bottom 0.3: v25.12,37.35 25.01,37.87 IC1.5 25.01,42.55 24.17,43.38 C10.1 | v20.68,32.27 20.05,31.64 18.14,31.64 17.04,30.54 IC5.2 16.94,29.31 C31.1
VNC-CTS  (via drill 0.4 pad 0.8)
  Top 0.3: v28.94,27.83 27.03,29.73 v24.49,29.73
  Bottom 0.3: IC1.35 23.51,30.71 v24.49,29.73 | U1.34 27.51,26.4 v28.94,27.83
VNC-DACK
  Bottom 0.3: U1.35 28.01,25.63 30.21,27.83 30.21,33.19 IC1.24
VNC-DREQ
  Bottom 0.3: IC1.23 31.19,33.83 31.48,33.54 31.48,27.83 28.51,24.86 U1.36
VNC-PROG  (via drill 0.4 pad 0.8)
  Top 0.3: v18.14,32.91 18.14,20.21 20.68,17.67 v20.68,8.14
  Bottom 0.3: U1.10 24.01,11.47 v20.68,8.14 R8.1 | IC1.39 19.57,34.33 v18.14,32.91
VNC-RST  (via drill 0.4 pad 0.8)
  Top 0.3: v20.05,33.54 19.41,32.91 19.41,20.84 22.59,17.67 v22.59,8.14
  Bottom 0.3: IC1.38 20.34,33.83 v20.05,33.54 | U1.9 24.51,10.07 v22.59,8.14 R10.1
VNC-RTS  (via drill 0.4 pad 0.8)
  Top 0.3: v27.35,27.83 27.35,28.14 27.03,28.46 v23.86,28.46
  Bottom 0.3: IC1.36 23.01,29.31 v23.86,28.46 | U1.33 27.01,27.17 v27.35,27.83
VNC-RXD
  Bottom 0.3: U1.32 IC1.29
VNC-TXD
  Bottom 0.254: U1.31 IC1.30

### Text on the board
Top: W2000A-USB-SD-Host
Document: Strapubox 2062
